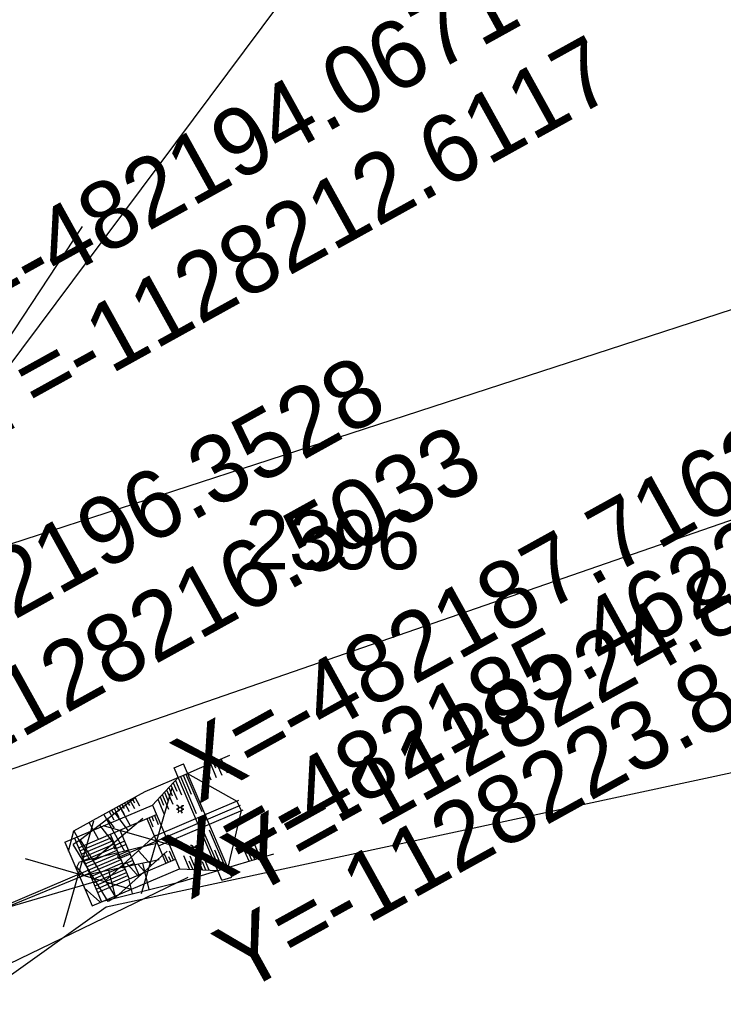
# Model space of a CAD drawing. Extents: x -483721 to -481876, y -1129170 to -1127366.
# Drawn here: x -482189.41 to -482169.09, y -1128228.85 to -1128200.12 of the extents above; entities that cross this region are included whole.
import ezdxf

# ---------------------------------------------------------------- set-up
doc = ezdxf.new("R2010")
doc.units = 0
for name, color, linetype in [('Hranice parcel', 7, 'Continuous'), ('kresba', 7, 'Continuous'), ('Parcelní čísla', 7, 'Continuous'), ('SO 01', 7, 'Continuous'), ('u_HV', 7, 'Continuous'), ('u_vytyčení', 7, 'Continuous'), ('ˇ12', 7, 'Continuous')]:
    doc.layers.add(name, color=color, linetype=linetype)

msp = doc.modelspace()

# ---------------------------------------------------------------- linework, layer by layer
at = {"layer": 'Hranice parcel'}
for p, q in [((-482132.99, -1128202.16), (-482204.83, -1128227.03)), ((-482194.8, -1128216.93), (-482167.83, -1128208.16)), ((-482186.92, -1128225.75), (-482161.18, -1128220.22)), ((-482198.83, -1128234.26), (-482186.92, -1128225.75))]:
    msp.add_line(p, q, dxfattribs=at)
msp.add_lwpolyline([(-482194.8, -1128216.93), (-482149.76, -1128156.56), (-482131.701, -1128127.511)], dxfattribs=at)
at = {"layer": 'kresba'}
for p, q in [((-482186.08, -1128222.6), (-482187.66, -1128223.82)), ((-482185.859, -1128223.202), (-482187.292, -1128224.416)), ((-482186.677, -1128223.467), (-482186.873, -1128223.213)), ((-482186.272, -1128223.551), (-482186.66, -1128223.048)), ((-482186.698, -1128223.913), (-482187.102, -1128223.389)), ((-482187.66, -1128223.82), (-482187.873, -1128223.951)), ((-482186.64, -1128225.47), (-482187.66, -1128223.82)), ((-482185.492, -1128223.685), (-482186.937, -1128224.989)), ((-482186.853, -1128225.601), (-482187.873, -1128223.951)), ((-482185.15, -1128224.14), (-482186.64, -1128225.47)), ((-482185.985, -1128224.13), (-482185.61, -1128224.551)), ((-482186.351, -1128224.461), (-482185.978, -1128224.879)), ((-482185.991, -1128224.524), (-482185.809, -1128224.728)), ((-482187.18, -1128225.01), (-482191.07, -1128226.15)), ((-482184.556, -1128224.904), (-482190.04, -1128227.55)), ((-482186.64, -1128225.47), (-482186.853, -1128225.601))]:
    msp.add_line(p, q, dxfattribs=at)
at = {"layer": 'SO 01'}
msp.add_line((-482202.984, -1128231.154), (-482187.403, -1128224.778), dxfattribs=at)
at = {"layer": 'u_HV'}
for p, q in [((-482184.286, -1128221.776), (-482183.338, -1128221.373)), ((-482184.286, -1128221.776), (-482183.338, -1128221.373)), ((-482184.286, -1128221.776), (-482183.338, -1128221.373)), ((-482183.827, -1128221.581), (-482183.761, -1128221.737)), ((-482183.749, -1128221.548), (-482183.578, -1128221.949)), ((-482183.67, -1128221.514), (-482183.604, -1128221.67)), ((-482183.592, -1128221.481), (-482183.421, -1128221.882)), ((-482184.955, -1128221.736), (-482184.679, -1128221.618)), ((-482183.572, -1128224.983), (-482184.955, -1128221.736)), ((-482183.283, -1128224.896), (-482184.679, -1128221.618)), ((-482184.566, -1128221.896), (-482184.29, -1128221.778)), ((-482184.062, -1128221.681), (-482183.891, -1128222.082)), ((-482183.984, -1128221.648), (-482183.917, -1128221.803)), ((-482183.905, -1128221.614), (-482183.735, -1128222.015)), ((-482185.578, -1128222.81), (-482184.837, -1128222.012)), ((-482184.98, -1128222.166), (-482184.878, -1128222.405)), ((-482184.916, -1128222.097), (-482184.738, -1128222.516)), ((-482184.772, -1128221.984), (-482184.315, -1128223.056)), ((-482184.693, -1128221.95), (-482184.463, -1128222.492)), ((-482184.615, -1128221.917), (-482184.154, -1128222.998)), ((-482185.233, -1128222.439), (-482185.131, -1128222.678)), ((-482185.17, -1128222.371), (-482184.992, -1128222.789)), ((-482185.107, -1128222.302), (-482185.005, -1128222.542)), ((-482185.043, -1128222.234), (-482184.865, -1128222.653)), ((-482186.384, -1128222.749), (-482186.249, -1128222.994)), ((-482186.31, -1128222.708), (-482186.245, -1128222.825)), ((-482186.235, -1128222.667), (-482186.1, -1128222.912)), ((-482186.161, -1128222.625), (-482186.096, -1128222.743)), ((-482186.086, -1128222.584), (-482185.951, -1128222.83)), ((-482185.521, -1128223.71), (-482183.087, -1128222.673)), ((-482185.424, -1128222.644), (-482185.25, -1128223.051)), ((-482185.36, -1128222.576), (-482185.26, -1128222.811)), ((-482185.297, -1128222.507), (-482185.116, -1128222.931)), ((-482195.577, -1128228.156), (-482183.036, -1128222.814)), ((-482188.108, -1128223.888), (-482185.578, -1128222.81)), ((-482186.832, -1128222.996), (-482186.832, -1128222.996)), ((-482186.832, -1128222.996), (-482186.696, -1128223.242)), ((-482186.757, -1128222.955), (-482186.692, -1128223.073)), ((-482186.682, -1128222.914), (-482186.682, -1128222.914)), ((-482186.682, -1128222.914), (-482186.547, -1128223.159)), ((-482186.608, -1128222.873), (-482186.543, -1128222.99)), ((-482186.533, -1128222.831), (-482186.398, -1128223.077)), ((-482186.459, -1128222.79), (-482186.394, -1128222.908)), ((-482185.578, -1128222.81), (-482184.794, -1128224.65)), ((-482185.403, -1128223.986), (-482182.96, -1128222.945)), ((-482184.849, -1128222.822), (-482184.884, -1128222.822)), ((-482184.71, -1128222.821), (-482184.675, -1128222.821)), ((-482187.715, -1128224.046), (-482185.461, -1128223.086)), ((-482185.737, -1128223.204), (-482185.188, -1128224.492)), ((-482185.677, -1128223.178), (-482185.567, -1128223.436)), ((-482185.599, -1128223.145), (-482185.546, -1128223.269)), ((-482185.52, -1128223.112), (-482185.41, -1128223.37)), ((-482186.519, -1128223.537), (-482185.97, -1128224.825)), ((-482183.626, -1128224.687), (-482184.082, -1128223.616)), ((-482183.462, -1128224.638), (-482183.929, -1128223.54)), ((-482188.108, -1128223.888), (-482187.324, -1128225.728)), ((-482187.832, -1128223.77), (-482187.048, -1128225.61)), ((-482187.675, -1128224.138), (-482186.755, -1128223.746)), ((-482187.636, -1128224.23), (-482186.716, -1128223.838)), ((-482186.795, -1128223.654), (-482186.246, -1128224.942)), ((-482186.381, -1128223.859), (-482186.702, -1128223.995)), ((-482182.296, -1128224.285), (-482182.462, -1128223.896)), ((-482187.597, -1128224.322), (-482186.677, -1128223.93)), ((-482187.558, -1128224.414), (-482186.638, -1128224.022)), ((-482187.519, -1128224.506), (-482186.599, -1128224.114)), ((-482186.702, -1128223.995), (-482186.663, -1128224.087)), ((-482186.342, -1128223.951), (-482186.663, -1128224.087)), ((-482186.264, -1128224.135), (-482186.585, -1128224.271)), ((-482184.972, -1128224.4), (-482185.082, -1128224.141)), ((-482184.441, -1128223.975), (-482184.476, -1128223.975)), ((-482184.302, -1128223.975), (-482184.267, -1128223.975)), ((-482183.544, -1128224.662), (-482183.778, -1128224.113)), ((-482182.788, -1128224.433), (-482182.955, -1128224.043)), ((-482182.706, -1128224.408), (-482182.828, -1128224.123)), ((-482182.624, -1128224.384), (-482182.79, -1128223.994)), ((-482182.542, -1128224.359), (-482182.648, -1128224.11)), ((-482182.46, -1128224.334), (-482182.626, -1128223.945)), ((-482182.378, -1128224.309), (-482182.469, -1128224.097)), ((-482187.48, -1128224.598), (-482186.559, -1128224.206)), ((-482187.405, -1128224.781), (-482186.485, -1128224.389)), ((-482187.166, -1128225.334), (-482184.912, -1128224.374)), ((-482186.585, -1128224.271), (-482186.546, -1128224.363)), ((-482186.225, -1128224.227), (-482186.546, -1128224.363)), ((-482186.146, -1128224.411), (-482186.467, -1128224.547)), ((-482185.128, -1128224.466), (-482185.238, -1128224.208)), ((-482185.05, -1128224.433), (-482185.103, -1128224.309)), ((-482184.507, -1128224.665), (-482184.673, -1128224.275)), ((-482184.416, -1128224.662), (-482184.515, -1128224.431)), ((-482184.324, -1128224.66), (-482184.484, -1128224.284)), ((-482184.224, -1128224.679), (-482184.326, -1128224.438)), ((-482184.129, -1128224.683), (-482184.295, -1128224.294)), ((-482184.035, -1128224.688), (-482184.137, -1128224.447)), ((-482183.94, -1128224.693), (-482184.106, -1128224.303)), ((-482183.112, -1128224.531), (-482182.072, -1128224.221)), ((-482182.294, -1128224.29), (-482182.294, -1128224.29)), ((-482187.362, -1128224.874), (-482186.442, -1128224.482)), ((-482187.324, -1128225.728), (-482184.794, -1128224.65)), ((-482187.323, -1128224.966), (-482186.403, -1128224.574)), ((-482187.284, -1128225.058), (-482186.364, -1128224.666)), ((-482187.244, -1128225.15), (-482186.324, -1128224.758)), ((-482186.467, -1128224.547), (-482186.428, -1128224.639)), ((-482186.107, -1128224.503), (-482186.428, -1128224.639)), ((-482184.794, -1128224.65), (-482183.69, -1128224.705)), ((-482183.401, -1128224.618), (-482183.112, -1128224.531)), ((-482187.205, -1128225.242), (-482186.285, -1128224.85)), ((-482183.572, -1128224.983), (-482183.283, -1128224.896))]:
    msp.add_line(p, q, dxfattribs=at)
for points in [[(-482187.913, -1128223.805), (-482187.85, -1128223.56), (-482185.79, -1128222.42), (-482184.562, -1128221.894)], [(-482184.562, -1128221.894), (-482183.138, -1128222.695), (-482183.02, -1128222.971), (-482183.401, -1128224.618)], [(-482184.849, -1128222.934), (-482184.884, -1128222.934)], [(-482184.884, -1128222.934), (-482184.849, -1128222.934), (-482184.814, -1128222.99), (-482184.849, -1128223.047)], [(-482184.745, -1128222.878), (-482184.814, -1128222.878), (-482184.849, -1128222.822)], [(-482184.849, -1128222.822), (-482184.814, -1128222.878), (-482184.849, -1128222.934)], [(-482184.745, -1128222.99), (-482184.814, -1128222.99), (-482184.849, -1128222.934), (-482184.814, -1128222.878), (-482184.745, -1128222.878), (-482184.71, -1128222.934), (-482184.745, -1128222.99)], [(-482184.675, -1128222.934), (-482184.71, -1128222.934), (-482184.745, -1128222.878), (-482184.71, -1128222.821)], [(-482184.71, -1128222.821), (-482184.745, -1128222.878)], [(-482184.71, -1128223.047), (-482184.745, -1128222.99), (-482184.71, -1128222.934), (-482184.675, -1128222.934)], [(-482184.441, -1128224.088), (-482184.476, -1128224.088)], [(-482184.476, -1128224.088), (-482184.441, -1128224.088), (-482184.406, -1128224.144), (-482184.441, -1128224.201)], [(-482184.337, -1128224.032), (-482184.406, -1128224.032), (-482184.441, -1128223.975)], [(-482184.441, -1128223.975), (-482184.406, -1128224.032), (-482184.441, -1128224.088)], [(-482184.337, -1128224.144), (-482184.406, -1128224.144), (-482184.441, -1128224.088), (-482184.406, -1128224.032), (-482184.337, -1128224.032), (-482184.302, -1128224.088), (-482184.337, -1128224.144)], [(-482184.267, -1128224.088), (-482184.302, -1128224.088), (-482184.337, -1128224.032), (-482184.302, -1128223.975)], [(-482184.302, -1128223.975), (-482184.337, -1128224.032)], [(-482184.302, -1128224.201), (-482184.337, -1128224.144), (-482184.302, -1128224.088), (-482184.267, -1128224.088)], [(-482186.974, -1128225.579), (-482184.7, -1128225.01), (-482183.401, -1128224.618)]]:
    msp.add_lwpolyline(points, dxfattribs=at)
at = {"layer": 'u_vytyčení'}
for p, q in [((-482185.022, -1128222.319), (-482185.902, -1128225.377)), ((-482187.277, -1128223.279), (-482188.156, -1128226.337)), ((-482183.933, -1128224.287), (-482186.991, -1128223.408)), ((-482186.187, -1128225.248), (-482189.245, -1128224.368))]:
    msp.add_line(p, q, dxfattribs=at)
at = {"layer": 'ˇ12'}
for p, q in [((-482187.61, -1128206.09), (-482193.09, -1128214.42)), ((-482187.85, -1128223.56), (-482185.79, -1128222.42)), ((-482186.54, -1128222.83), (-482186.21, -1128223.42)), ((-482187.41, -1128223.32), (-482187.15, -1128223.79)), ((-482186.98, -1128223.08), (-482186.39, -1128224.14)), ((-482188, -1128224.14), (-482187.85, -1128223.56)), ((-482187.85, -1128223.56), (-482187.4, -1128224.38)), ((-482187.69, -1128224.45), (-482185.42, -1128223.9)), ((-482187.76, -1128224.61), (-482187.69, -1128224.45)), ((-482185.38, -1128224.39), (-482187.55, -1128224.85)), ((-482187.55, -1128224.85), (-482187.76, -1128224.61)), ((-482186.64, -1128225.49), (-482186.84, -1128224.7)), ((-482185.67, -1128225.25), (-482185.86, -1128224.49)), ((-482186.15, -1128225.37), (-482186.25, -1128224.98)), ((-482187.55, -1128225.2), (-482187.1, -1128225.61))]:
    msp.add_line(p, q, dxfattribs=at)

# ---------------------------------------------------------------- texts
at = {"layer": 'Parcelní čísla'}
msp.add_text('2396', height=1.7, dxfattribs=at).set_placement((-482182.898, -1128215.997))
at = {"layer": 'u_vytyčení'}
for s, p in [('X=-482194.0671', (-482191.927, -1128209.681)), ('Y=-1128212.6117', (-482190.429, -1128212.388)), ('X=-482196.3528', (-482195.794, -1128220.912)), ('X=-482187.7163', (-482184.249, -1128222.789)), ('Y=-1128216.5033', (-482194.296, -1128223.619)), ('Y=-1128224.8077', (-482182.752, -1128225.496)), ('X=-482185.4623', (-482184.509, -1128225.57)), ('Y=-1128223.8477', (-482183.011, -1128228.277))]:
    msp.add_text(s, height=1.96875, rotation=28.9559, dxfattribs=at).set_placement(p)

doc.saveas('drawing.dxf')
